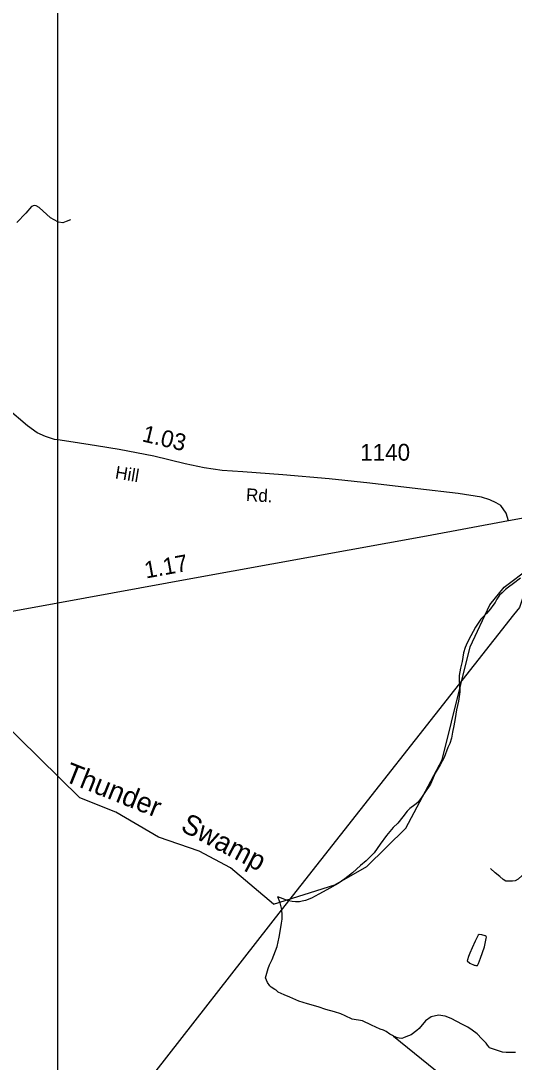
# Model space of a CAD drawing. Extents: x 2206922 to 2357709, y 510027 to 673830.
# Drawn here: x 2268610 to 2272282, y 528022 to 535777 of the extents above; entities that cross this region are included whole.
import ezdxf

# ---------------------------------------------------------------- set-up
doc = ezdxf.new("R2010")
doc.units = 0
for name, color, linetype in [('Exist Hydrographic Creek Single Shore', 7, 'Continuous'), ('Exist Hydrographic Creek Single Shore Label', 7, 'Continuous'), ('Exist Hydrographic Misc Water Feature', 7, 'Continuous'), ('Exist Road Non-System Type 51', 7, 'Continuous'), ('Exist Road Primary NC Attributed', 7, 'Continuous'), ('Exist Road Primary NC Service Mileage Hundredths English Label', 7, 'Continuous'), ('Exist Road Secondary Mileage Hundredths English Label', 7, 'Continuous'), ('Exist Road Secondary Type 51 Attributed', 7, 'Continuous'), ('Exist Road Secondary Type 51 Label', 7, 'Continuous'), ('Exist Road Secondary Type 51 Number Label', 7, 'Continuous'), ('Exist Utilities Electrical Transmission Line', 7, 'Continuous'), ('Map Preparation Inset Cut Line', 7, 'Continuous')]:
    doc.layers.add(name, color=color, linetype=linetype)

msp = doc.modelspace()

# ---------------------------------------------------------------- linework, layer by layer
at = {"layer": 'Exist Hydrographic Creek Single Shore'}
for points in [[(2270489.8, 529197.5), (2270945.9, 529342.5), (2271185.8, 529478.7), (2271474.9, 529764.8), (2271744.8, 530274.2), (2271953.9, 531116.2), (2272100.9, 531428.1), (2272207.8, 531560.4), (2272397.9, 531704.1), (2272605.8, 531788.5), (2273037.8, 531894.5), (2273344.8, 532013), (2273434.8, 532181.7), (2273417, 532313.3), (2273161.9, 532803.8), (2273116.8, 533218), (2273138.9, 533509.4), (2273095.8, 533693.9), (2273100.8, 533969.3), (2273584.9, 534838.5), (2273694.8, 535472.5)], [(2270489.8, 529197.5), (2270169.8, 529469.6), (2269935.8, 529592.4), (2269634.8, 529696.9), (2269316.7, 529883.6), (2269048.7, 529990.7), (2268140.8, 530881.3), (2267901, 531203.2), (2267865.6, 531254.7), (2267747.8, 531370.2), (2267694.8, 531395.4), (2267394.8, 531467.1), (2267168.8, 531563.4), (2266843.8, 531609.4), (2266475.7, 531780.7), (2266262.3, 531935.8), (2265872.7, 532150.4), (2265292.8, 532680.2), (2264456.8, 533861.4), (2263950.7, 534589.8), (2263234.7, 535391.3)], [(2272099.1, 528128.8), (2272096.8, 528132.8), (2272082.9, 528148.7), (2272072.6, 528164.3), (2272042.3, 528196.1), (2272005.6, 528234.1), (2271969.5, 528259.4), (2271937.3, 528283.3), (2271897.1, 528302.7), (2271812.8, 528347.9), (2271769.2, 528365.4), (2271718.9, 528373), (2271662.9, 528358.7), (2271621.3, 528330.1), (2271574.2, 528271.9), (2271556.1, 528257.6), (2271514.1, 528225.4), (2271474.3, 528210.7), (2271456.9, 528202.8), (2271444.6, 528198.6), (2271426.7, 528200.5), (2271412.6, 528202.2), (2271400.3, 528208.1), (2271384.3, 528216.2), (2271376.3, 528221.9), (2271356.2, 528231.8), (2271328.1, 528249.4), (2271308, 528259.3), (2271283.8, 528269), (2271219.8, 528296.5), (2271153.2, 528329.7), (2271077.1, 528343.1), (2271023.2, 528368.3), (2270991, 528382.1), (2270944.9, 528398), (2270880.9, 528415.3), (2270822.4, 528434.6), (2270742.7, 528456), (2270678.3, 528477), (2270612.3, 528506.5), (2270569.6, 528524.3), (2270525.7, 528543.8), (2270509.3, 528557.7), (2270501.3, 528563.7), (2270473.2, 528581.4), (2270463.6, 528591.3), (2270445.3, 528615.1), (2270431, 528651), (2270449.9, 528719.1), (2270461.7, 528746.9), (2270479.6, 528787.2), (2270492.9, 528819.2), (2270518.5, 528883.5), (2270531.9, 528953.7), (2270543.4, 529009.6), (2270548.9, 529057.8), (2270554.6, 529087.7), (2270554.2, 529115.8), (2270552.2, 529159.5), (2270539.7, 529209.6), (2270523.3, 529253.5)], [(2271384.3, 528216.2), (2271748.1, 527920.5), (2272048.7, 527507.2), (2272299.2, 527206.5), (2272361.8, 526993.6), (2272506.3, 526487.6)], [(2272291, 528094.6), (2272251, 528094.1), (2272235.2, 528094.1), (2272223.4, 528093.8), (2272195.1, 528095.6), (2272165.3, 528105.4), (2272099.1, 528128.8)]]:
    msp.add_lwpolyline(points, dxfattribs=at)
at = {"layer": 'Exist Hydrographic Misc Water Feature'}
for points in [[(2272330, 531627.1), (2272276, 531586.6), (2272240.8, 531558.2), (2272216.8, 531542), (2272192.8, 531518), (2272173.1, 531499.5), (2272153.2, 531469.6), (2272139.5, 531445.3), (2272121.9, 531423.3), (2272106.1, 531397.3), (2272076.3, 531362.8), (2272034.9, 531320.4), (2271995.1, 531260.3), (2271960.3, 531195.8), (2271932.4, 531143.6), (2271917, 531109.5), (2271905.1, 531069.5), (2271895.7, 531005.2), (2271882.3, 530955.3), (2271872.9, 530901.2), (2271871.5, 530859.2), (2271875.4, 530837.1), (2271876.4, 530779.4), (2271868.4, 530711.2), (2271853.4, 530647), (2271843.8, 530581.1), (2271832.3, 530526.9), (2271823.1, 530478.9), (2271815.3, 530435), (2271803.4, 530395), (2271787.8, 530364.5), (2271760.5, 530290.4), (2271731.2, 530236), (2271693.9, 530173.9), (2271658.6, 530091.6), (2271617.2, 530031.4), (2271591.6, 529993), (2271563.9, 529956.7), (2271542.2, 529938.5), (2271504.2, 529910.1), (2271484.3, 529890), (2271453, 529849.7), (2271415.7, 529801.4), (2271381.8, 529769.2), (2271330.6, 529708.8), (2271283.2, 529646.2), (2271239.3, 529579.8), (2271180.3, 529521.4), (2271136.8, 529487), (2271079.2, 529432.4), (2271021.5, 529388), (2270972.1, 529353.7), (2270888.3, 529304.7), (2270828.8, 529274.3), (2270773.2, 529243.7), (2270729.3, 529225.2), (2270703.1, 529221.1), (2270683.2, 529216.8), (2270653.5, 529216.8), (2270629.1, 529218.4), (2270601.6, 529224.2), (2270579.7, 529229.9), (2270563, 529237.7), (2270543.2, 529245.6), (2270523.3, 529253.5)], [(2272046.2, 528839.9), (2272059.9, 528882), (2272072.8, 528944.1), (2272075.1, 528952.3), (2272073, 528958.2), (2272065.1, 528963.9), (2272041.1, 528969.6), (2272021, 528971.8), (2272013, 528967.7), (2271991.6, 528923.5), (2271970.1, 528873.2), (2271952.3, 528835), (2271942.8, 528808.8), (2271935, 528784.8), (2271931.2, 528776.9), (2271951, 528758.9), (2271983.2, 528745.1), (2271989.2, 528743.4), (2271997, 528741.4), (2272008.9, 528741.7), (2272016.7, 528757.5), (2272030.8, 528796), (2272046.2, 528839.9)]]:
    msp.add_lwpolyline(points, dxfattribs=at)
at = {"layer": 'Exist Road Non-System Type 51'}
for points in [[(2268884.2, 534279.7), (2268830.4, 534310.5), (2268745.8, 534387.5), (2268723.6, 534399.4), (2268707.6, 534401.3), (2268687.7, 534393.1), (2268646.1, 534344.8), (2268580.9, 534274.1)], [(2268980.4, 534295.9), (2268946.6, 534281.5), (2268922.8, 534273.4), (2268888.7, 534277.1), (2268884.2, 534279.7)], [(2273024.5, 530164.7), (2273000.5, 530138.2), (2272900.9, 530035.1), (2272777, 529895.3), (2272679.2, 529788.8), (2272497.5, 529586.1), (2272396.2, 529476), (2272342.1, 529413.1), (2272310.7, 529385.1), (2272289.7, 529372.9), (2272270.5, 529369.4), (2272247.8, 529369.4), (2272219.8, 529371.1), (2272200.6, 529383.4), (2272176.2, 529404.3), (2272139.5, 529432.3), (2272104.6, 529463.7)]]:
    msp.add_lwpolyline(points, dxfattribs=at)
at = {"layer": 'Exist Road Primary NC Attributed'}
for points in [[(2272966.7, 532182.1), (2272888.5, 532169), (2272555.9, 532109.7), (2272239.1, 532053.3)], [(2272239.1, 532053.3), (2271628, 531939.6), (2269901.9, 531625.8), (2268884.2, 531440.2), (2268148.4, 531306.1), (2266894.4, 531072.8), (2266430.7, 530983.1), (2266171.3, 530939.7)]]:
    msp.add_lwpolyline(points, dxfattribs=at)
at = {"layer": 'Exist Road Secondary Type 51 Attributed'}
msp.add_lwpolyline([(2272239.1, 532053.3), (2272222.2, 532109.2), (2272182, 532166.4), (2272148.2, 532188.5), (2272101.4, 532210.6), (2272037.8, 532230.1), (2271863.8, 532256), (2271563.7, 532292.4), (2271207.8, 532332.7), (2270905.2, 532366.5), (2270559.7, 532395.1), (2270261, 532418.5), (2270107.7, 532428.9), (2269975.2, 532447.1), (2269832.4, 532478.3), (2269598.6, 532534.1), (2269341.4, 532583.5), (2269172.6, 532612.1), (2268998.5, 532638.1), (2268884.2, 532656.5), (2268860.8, 532660.2), (2268793.3, 532681), (2268731, 532708.3), (2268658.2, 532761.6), (2268507.6, 532888.9)], dxfattribs=at)
at = {"layer": 'Exist Utilities Electrical Transmission Line'}
msp.add_lwpolyline([(2272555.9, 532109.7), (2272335.4, 531453.1), (2272321.9, 531406.9), (2272276.4, 531354.5), (2270548, 529153.6), (2269517, 527832.5), (2269483.5, 527788.2), (2269447.9, 527739.9), (2268884.2, 527012.8)], dxfattribs=at)
at = {"layer": 'Map Preparation Inset Cut Line'}
msp.add_lwpolyline([(2268884.2, 521583.5), (2268884.2, 540252.9), (2271763.2, 540252.9)], dxfattribs=at)

# ---------------------------------------------------------------- texts
at = {"layer": 'Exist Hydrographic Creek Single Shore Label'}
for s, rotation, p in [('Thunder', 338.22883, (2268924.6, 530118)), ('Swamp', 332.3212, (2269790.8, 529749.9))]:
    msp.add_text(s, height=150, rotation=rotation, dxfattribs=at).set_placement(p)
at = {"layer": 'Exist Road Primary NC Service Mileage Hundredths English Label'}
msp.add_text('1.17', height=125, rotation=10.33278, dxfattribs=at).set_placement((2269541.1, 531623.5))
at = {"layer": 'Exist Road Secondary Mileage Hundredths English Label'}
msp.add_text('1.03', height=125, rotation=346.55737, dxfattribs=at).set_placement((2269505.6, 532646.6))
at = {"layer": 'Exist Road Secondary Type 51 Label'}
for s, rotation, p in [('Hill', 350.56493, (2269306.9, 532369.5)), ('Rd.', 356.8961, (2270283.6, 532201.2))]:
    msp.add_text(s, height=95, rotation=rotation, dxfattribs=at).set_placement(p)
at = {"layer": 'Exist Road Secondary Type 51 Number Label'}
msp.add_text('1140', height=125, dxfattribs=at).set_placement((2271135.2, 532501.3))

doc.saveas('drawing.dxf')
